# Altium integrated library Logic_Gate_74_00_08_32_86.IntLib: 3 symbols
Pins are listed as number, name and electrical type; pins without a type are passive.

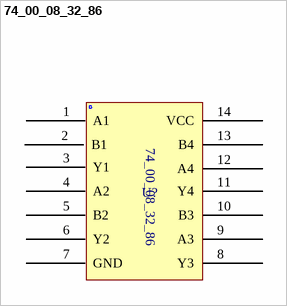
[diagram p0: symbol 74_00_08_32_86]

## 74_00_08_32_86
designator U?  (value not drawn)
footprint 74_00_08_32_86
pins: 1 A1, 2 B1, 3 Y1, 4 A2, 5 B2, 6 Y2, 7 GND, 8 Y3, 9 A3, 10 B3, 11 Y4, 12 A4, 13 B4, 14 VCC


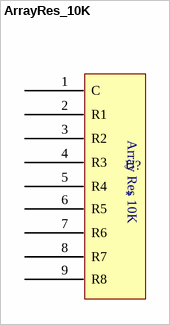
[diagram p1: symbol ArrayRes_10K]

## ArrayRes_10K
designator U?
footprint ArrayRes_10K
pins: 1 C, 2 R1, 3 R2, 4 R3, 5 R4, 6 R5, 7 R6, 8 R7, 9 R8


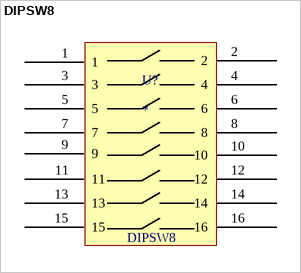
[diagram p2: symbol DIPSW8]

## DIPSW8
designator U?
footprint DIPSW8
pins: 1, 2, 3, 4, 5, 6, 7, 8, 9, 10, 11, 12, 13, 14, 15, 16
